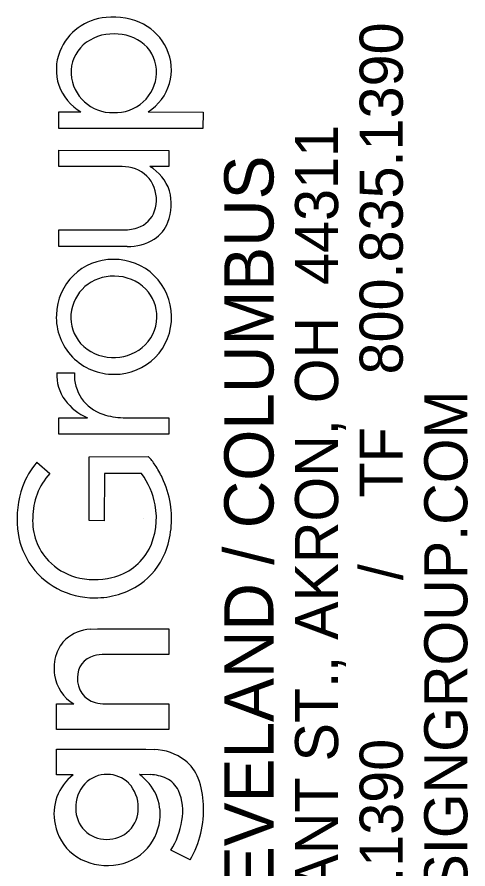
# Model space of a CAD drawing. Extents: x -0.4 to 34, y 0 to 22.
# Drawn here: x 32.603 to 33.125, y 3.594 to 4.581 of the extents above; entities that cross this region are included whole.
import ezdxf

# ---------------------------------------------------------------- set-up
doc = ezdxf.new("R2010")
doc.units = 0
doc.layers.add('_CIVIL_CONSTRUCTION', color=7, linetype='Continuous')

msp = doc.modelspace()

# ---------------------------------------------------------------- linework, layer by layer
at = {"layer": '_CIVIL_CONSTRUCTION'}
for p, q in [((32.65152, 4.47113), (32.67709, 4.47115)), ((32.65152, 4.45215), (32.65152, 4.47113)), ((32.75491, 4.47132), (32.81858, 4.47108)), ((32.81858, 4.47108), (32.81843, 4.45215)), ((32.81843, 4.45215), (32.65152, 4.45215)), ((32.65152, 4.40801), (32.65153, 4.42672)), ((32.65153, 4.42672), (32.7791, 4.42664)), ((32.7791, 4.42664), (32.77908, 4.40796)), ((32.7249, 4.40796), (32.65152, 4.40801)), ((32.7328, 4.40727), (32.7249, 4.40796)), ((32.77908, 4.40796), (32.75689, 4.40796)), ((32.65154, 4.33443), (32.72905, 4.3345)), ((32.65165, 4.31543), (32.65154, 4.33443)), ((32.73073, 4.31543), (32.65165, 4.31543)), ((32.64932, 4.16907), (32.66978, 4.16907)), ((32.65152, 4.11699), (32.68476, 4.117)), ((32.65152, 4.098), (32.65152, 4.11699)), ((32.72605, 4.11703), (32.7791, 4.11696)), ((32.7791, 4.11696), (32.77903, 4.098)), ((32.77903, 4.098), (32.65152, 4.098)), ((32.62636, 4.06548), (32.64114, 4.05241)), ((32.6868, 4.07185), (32.75516, 4.07192)), ((32.6868, 3.99778), (32.6868, 4.07185)), ((32.70448, 4.05241), (32.70432, 3.99775)), ((32.74737, 4.05227), (32.70448, 4.05241)), ((32.70432, 3.99775), (32.6868, 3.99778)), ((32.75, 4), (32.75, 4)), ((32.68784, 3.8722), (32.69634, 3.87266)), ((32.69634, 3.87266), (32.77916, 3.87266)), ((32.77916, 3.87266), (32.77917, 3.84287)), ((32.77917, 3.84287), (32.70485, 3.8428)), ((32.64888, 3.7855), (32.66897, 3.78555)), ((32.64888, 3.75569), (32.64888, 3.7855)), ((32.70568, 3.78555), (32.77915, 3.78555)), ((32.77915, 3.78555), (32.77917, 3.75579)), ((32.77917, 3.75579), (32.64888, 3.75569)), ((32.6489, 3.70336), (32.64889, 3.73322)), ((32.64889, 3.73322), (32.75236, 3.73322)), ((32.75236, 3.73322), (32.76191, 3.73285)), ((32.66836, 3.70336), (32.6489, 3.70336)), ((32.75763, 3.70356), (32.74487, 3.70361)), ((32.8036, 3.60491), (32.7812, 3.61598))]:
    msp.add_line(p, q, dxfattribs=at)
for points in [[(32.75491, 4.47132), (32.81858, 4.47108), (32.81843, 4.45215), (32.65152, 4.45215)], [(32.65152, 4.45215), (32.65152, 4.47113), (32.67709, 4.47115)], [(32.7328, 4.40727), (32.7249, 4.40796), (32.65152, 4.40801), (32.65153, 4.42672), (32.7791, 4.42664), (32.77908, 4.40796), (32.75689, 4.40796)], [(32.73073, 4.31543), (32.65165, 4.31543), (32.65154, 4.33443), (32.72905, 4.3345)], [(32.64932, 4.16907), (32.66978, 4.16907)], [(32.72605, 4.11703), (32.7791, 4.11696), (32.77903, 4.098), (32.65152, 4.098)], [(32.65152, 4.098), (32.65152, 4.11699), (32.68476, 4.117)], [(32.62636, 4.06548), (32.64114, 4.05241)], [(32.74737, 4.05227), (32.70448, 4.05241), (32.70432, 3.99775), (32.6868, 3.99778), (32.6868, 4.07185), (32.75516, 4.07192)], [(32.68784, 3.8722), (32.69634, 3.87266), (32.77916, 3.87266), (32.77917, 3.84287), (32.70485, 3.8428)], [(32.64888, 3.75569), (32.64888, 3.7855), (32.66897, 3.78555)], [(32.70568, 3.78555), (32.77915, 3.78555), (32.77917, 3.75579), (32.64888, 3.75569)], [(32.66836, 3.70336), (32.6489, 3.70336), (32.64889, 3.73322), (32.75236, 3.73322), (32.76191, 3.73285)], [(32.75763, 3.70356), (32.74487, 3.70361)], [(32.8036, 3.60491), (32.7812, 3.61598)]]:
    msp.add_lwpolyline(points, dxfattribs=at)
for centre, radius, start, end in [((32.71081, 4.51825), 0.06243, 93.98662, 158.31194), ((32.71081, 4.51825), 0.06243, 93.98662, 158.31194), ((32.71557, 4.5065), 0.07459, 62.68889, 97.01346), ((32.71557, 4.5065), 0.07459, 62.68889, 97.01346), ((32.72123, 4.51914), 0.06076, 25.06574, 61.96022), ((32.72123, 4.51914), 0.06076, 25.06574, 61.96022), ((32.71379, 4.51017), 0.05134, 87.89653, 131.18123), ((32.71379, 4.51017), 0.05134, 87.89653, 131.18123), ((32.7175, 4.51023), 0.05127, 49.90886, 92.03625), ((32.7175, 4.51023), 0.05127, 49.90886, 92.03625), ((32.72154, 4.51733), 0.04327, 358.04871, 47.94467), ((32.72154, 4.51733), 0.04327, 358.04871, 47.94467), ((32.70695, 4.52016), 0.05815, 158.65601, 198.17101), ((32.70695, 4.52016), 0.05815, 158.65601, 198.17101), ((32.7092, 4.51674), 0.04338, 132.32887, 182.09489), ((32.7092, 4.51674), 0.04338, 132.32887, 182.09489), ((32.7245, 4.52004), 0.05743, 301.97764, 25.64176), ((32.7245, 4.52004), 0.05743, 301.97764, 25.64176), ((32.71352, 4.51815), 0.04776, 183.59741, 271.7045), ((32.71352, 4.51815), 0.04776, 183.59741, 271.7045), ((32.71717, 4.51801), 0.04766, 267.31494, 357.4019), ((32.71717, 4.51801), 0.04766, 267.31494, 357.4019), ((32.7103, 4.52433), 0.0627, 200.83985, 238.01619), ((32.7103, 4.52433), 0.0627, 200.83985, 238.01619), ((32.72711, 4.36998), 0.03772, 33.50082, 81.32954), ((32.72711, 4.36998), 0.03772, 33.50082, 81.32954), ((32.73239, 4.36485), 0.04959, 17.62209, 60.38974), ((32.73239, 4.36485), 0.04959, 17.62209, 60.38974), ((32.72414, 4.3695), 0.04048, 346.56179, 31.75389), ((32.72414, 4.3695), 0.04048, 346.56179, 31.75389), ((32.72343, 4.36415), 0.05838, 339.16197, 15.61485), ((32.72343, 4.36415), 0.05838, 339.16197, 15.61485), ((32.73371, 4.36616), 0.03042, 294.63214, 348.48625), ((32.73371, 4.36616), 0.03042, 294.63214, 348.48625), ((32.739, 4.35901), 0.04201, 303.10391, 338.15613), ((32.739, 4.35901), 0.04201, 303.10391, 338.15613), ((32.72747, 4.38081), 0.04633, 271.95199, 294.08943), ((32.72747, 4.38081), 0.04633, 271.95199, 294.08943), ((32.7321, 4.37256), 0.05715, 268.62699, 301.47779), ((32.7321, 4.37256), 0.05715, 268.62699, 301.47779), ((32.71435, 4.23484), 0.06552, 89.48213, 178.77752), ((32.71435, 4.23484), 0.06552, 89.48213, 178.77752), ((32.71582, 4.23414), 0.06623, 0.42265, 90.7613), ((32.71582, 4.23414), 0.06623, 0.42265, 90.7613), ((32.71397, 4.23244), 0.04846, 87.68827, 175.01696), ((32.71397, 4.23244), 0.04846, 87.68827, 175.01696), ((32.71659, 4.23036), 0.05052, 44.91202, 90.75914), ((32.71659, 4.23036), 0.05052, 44.91202, 90.75914), ((32.71955, 4.23452), 0.04549, 358.32279, 43.83486), ((32.71955, 4.23452), 0.04549, 358.32279, 43.83486), ((32.71483, 4.2334), 0.06606, 177.53728, 270.94524), ((32.71483, 4.2334), 0.06606, 177.53728, 270.94524), ((32.71085, 4.23311), 0.0453, 175.51467, 221.42047), ((32.71085, 4.23311), 0.0453, 175.51467, 221.42047), ((32.71671, 4.23271), 0.06536, 269.30834, 1.67905), ((32.71671, 4.23271), 0.06536, 269.30834, 1.67905), ((32.71931, 4.23374), 0.04572, 308.90382, 359.30947), ((32.71931, 4.23374), 0.04572, 308.90382, 359.30947), ((32.71399, 4.23734), 0.05046, 222.66255, 268.37331), ((32.71399, 4.23734), 0.05046, 222.66255, 268.37331), ((32.71567, 4.23859), 0.05178, 266.55312, 308.67253), ((32.71567, 4.23859), 0.05178, 266.55312, 308.67253), ((32.69878, 4.16662), 0.04952, 177.16211, 216.28024), ((32.69878, 4.16662), 0.04952, 177.16211, 216.28024), ((32.71735, 4.16638), 0.04764, 176.76988, 252.15044), ((32.71735, 4.16638), 0.04764, 176.76988, 252.15044), ((32.70975, 4.17555), 0.06366, 216.91526, 246.88619), ((32.70975, 4.17555), 0.06366, 216.91526, 246.88619), ((32.7269, 4.19175), 0.07473, 251.13884, 269.34694), ((32.7269, 4.19175), 0.07473, 251.13884, 269.34694), ((32.70163, 4.00187), 0.09855, 139.79476, 159.13696), ((32.70163, 4.00187), 0.09855, 139.79476, 159.13696), ((32.72498, 4.03937), 0.04438, 30.98913, 47.16099), ((32.72498, 4.03937), 0.04438, 30.98913, 47.16099), ((32.67091, 4.00018), 0.11106, 25.30315, 33.96179), ((32.67091, 4.00018), 0.11106, 25.30315, 33.96179), ((32.69899, 4.00079), 0.07753, 138.25804, 179.70064), ((32.69899, 4.00079), 0.07753, 138.25804, 179.70064), ((32.67889, 4.00099), 0.08556, 10.07509, 36.83189), ((32.67889, 4.00099), 0.08556, 10.07509, 36.83189), ((32.6704, 3.99987), 0.11166, 8.80339, 25.33484), ((32.6704, 3.99987), 0.11166, 8.80339, 25.33484), ((32.7187, 3.99968), 0.11536, 161.14379, 185.62812), ((32.7187, 3.99968), 0.11536, 161.14379, 185.62812), ((32.67564, 3.99977), 0.10649, 338.28866, 9.28548), ((32.67564, 3.99977), 0.10649, 338.28866, 9.28548), ((32.68425, 4.00057), 0.08036, 333.46689, 11.03668), ((32.68425, 4.00057), 0.08036, 333.46689, 11.03668), ((32.68811, 3.99732), 0.06676, 176.66577, 223.6912), ((32.68811, 3.99732), 0.06676, 176.66577, 223.6912), ((32.69336, 3.99699), 0.08987, 185.50773, 212.01294), ((32.69336, 3.99699), 0.08987, 185.50773, 212.01294), ((32.69868, 3.99547), 0.0652, 282.88151, 331.81475), ((32.69868, 3.99547), 0.0652, 282.88151, 331.81475), ((32.69835, 3.99168), 0.08241, 305.03061, 337.67573), ((32.69835, 3.99168), 0.08241, 305.03061, 337.67573), ((32.69211, 3.99748), 0.08908, 212.70222, 270.71399), ((32.69211, 3.99748), 0.08908, 212.70222, 270.71399), ((32.69045, 4.00011), 0.07039, 224.02147, 253.88), ((32.69045, 4.00011), 0.07039, 224.02147, 253.88), ((32.69318, 4.01254), 0.08309, 254.45353, 283.9512), ((32.69318, 4.01254), 0.08309, 254.45353, 283.9512), ((32.69429, 3.99979), 0.09138, 269.3273, 304.19632), ((32.69429, 3.99979), 0.09138, 269.3273, 304.19632), ((32.69216, 3.82251), 0.04988, 94.97056, 130.22484), ((32.69216, 3.82251), 0.04988, 94.97056, 130.22484), ((32.68694, 3.83085), 0.04016, 132.22383, 161.68229), ((32.68694, 3.83085), 0.04016, 132.22383, 161.68229), ((32.70217, 3.82642), 0.05602, 162.27398, 187.79173), ((32.70217, 3.82642), 0.05602, 162.27398, 187.79173), ((32.69828, 3.81689), 0.02498, 103.68683, 182.21395), ((32.69828, 3.81689), 0.02498, 103.68683, 182.21395), ((32.70453, 3.79679), 0.04601, 89.60515, 105.33026), ((32.70453, 3.79679), 0.04601, 89.60515, 105.33026), ((32.69372, 3.82624), 0.04763, 188.96462, 238.69865), ((32.69372, 3.82624), 0.04763, 188.96462, 238.69865), ((32.7008, 3.81381), 0.02757, 175.58441, 255.13816), ((32.7008, 3.81381), 0.02757, 175.58441, 255.13816), ((32.70529, 3.82769), 0.04215, 254.08913, 270.52838), ((32.70529, 3.82769), 0.04215, 254.08913, 270.52838), ((32.75907, 3.66789), 0.06503, 53.40344, 87.49062), ((32.75907, 3.66789), 0.06503, 53.40344, 87.49062), ((32.76517, 3.68039), 0.05141, 21.60748, 50.5577), ((32.76517, 3.68039), 0.05141, 21.60748, 50.5577), ((32.70292, 3.65813), 0.05692, 127.37482, 192.22468), ((32.70292, 3.65813), 0.05692, 127.37482, 192.22468), ((32.70693, 3.66927), 0.0346, 88.47302, 136.42562), ((32.70693, 3.66927), 0.0346, 88.47302, 136.42562), ((32.70814, 3.66963), 0.03424, 44.27195, 90.47623), ((32.70814, 3.66963), 0.03424, 44.27195, 90.47623), ((32.71421, 3.65829), 0.05472, 352.1125, 55.92295), ((32.71421, 3.65829), 0.05472, 352.1125, 55.92295), ((32.75666, 3.65725), 0.04633, 65.01687, 88.8011), ((32.75666, 3.65725), 0.04633, 65.01687, 88.8011), ((32.71141, 3.66602), 0.0401, 137.46739, 182.33237), ((32.71141, 3.66602), 0.0401, 137.46739, 182.33237), ((32.70368, 3.666), 0.03996, 358.57141, 43.53765), ((32.70368, 3.666), 0.03996, 358.57141, 43.53765), ((32.7626, 3.67155), 0.03085, 26.26808, 63.80301), ((32.7626, 3.67155), 0.03085, 26.26808, 63.80301), ((32.73069, 3.66714), 0.08835, 1.15143, 21.3627), ((32.73069, 3.66714), 0.08835, 1.15143, 21.3627), ((32.73565, 3.66154), 0.05953, 349.30734, 23.43071), ((32.73565, 3.66154), 0.05953, 349.30734, 23.43071), ((32.70645, 3.6637), 0.03511, 178.88208, 271.08374), ((32.70645, 3.6637), 0.03511, 178.88208, 271.08374), ((32.70818, 3.66404), 0.03546, 268.27882, 1.55016), ((32.70818, 3.66404), 0.03546, 268.27882, 1.55016), ((32.70538, 3.66244), 0.11383, 329.6388, 3.25998), ((32.70538, 3.66244), 0.11383, 329.6388, 3.25998), ((32.70463, 3.65696), 0.05837, 190.75182, 231.28919), ((32.70463, 3.65696), 0.05837, 190.75182, 231.28919), ((32.70988, 3.65708), 0.05887, 313.74196, 353.8554), ((32.70988, 3.65708), 0.05887, 313.74196, 353.8554), ((32.70738, 3.66334), 0.08771, 327.31495, 351.57478), ((32.70738, 3.66334), 0.08771, 327.31495, 351.57478), ((32.70954, 3.65901), 0.06051, 269.6361, 312.70877), ((32.70954, 3.65901), 0.06051, 269.6361, 312.70877), ((32.70632, 3.66112), 0.06269, 232.46061, 272.59022), ((32.70632, 3.66112), 0.06269, 232.46061, 272.59022)]:
    msp.add_arc(centre, radius, start, end, dxfattribs=at)

# ---------------------------------------------------------------- texts
for s, height, p in [('800.835.1390', 0.0498462, (33.04966, 4.1671)), ('450 GRANT ST., AKRON, OH  44311', 0.0498462, (32.97489, 3.33738)), ('AKRON / CLEVELAND / COLUMBUS', 0.056969, (32.90012, 3.138)), ('ENVDESIGNGROUP.COM', 0.0498462, (33.12443, 3.33738)), ('TF', 0.049846, (33.04966, 4.0246)), ('/  ', 0.049846, (33.04966, 3.92884)), ('330.375.1390', 0.0498462, (33.04966, 3.33738))]:
    msp.add_text(s, height=height, rotation=90, dxfattribs=at).set_placement(p)

doc.saveas('drawing.dxf')
